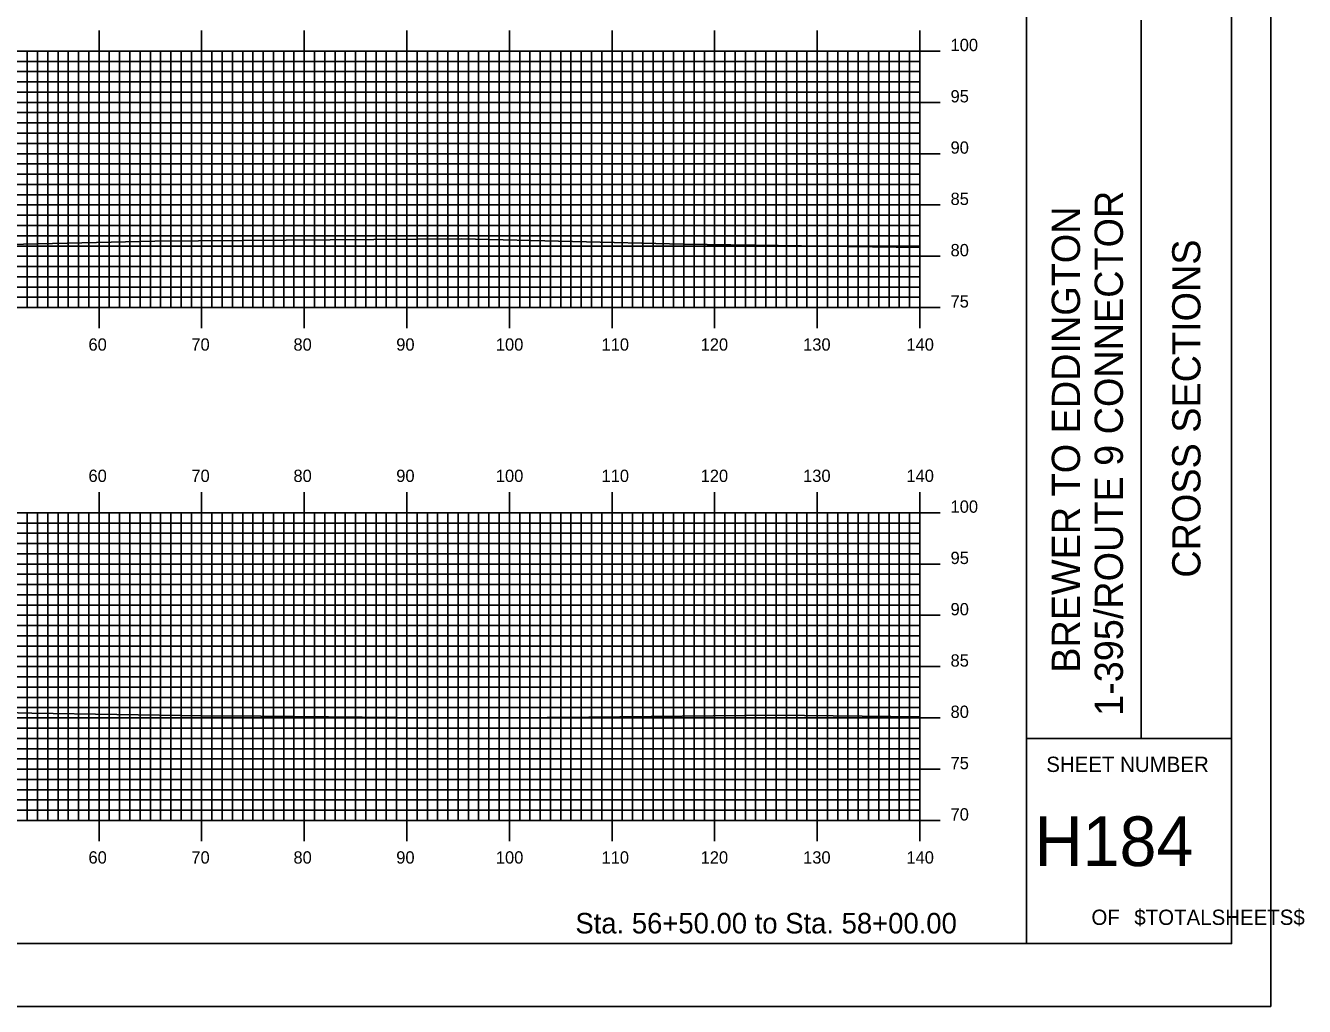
# Model space of a CAD drawing. Extents: x 1757069 to 1757412, y 442591 to 442811.
# Drawn here: x 1757287.4 to 1757412.1, y 442590.5 to 442686.2 of the extents above; entities that cross this region are included whole.
import ezdxf

# ---------------------------------------------------------------- set-up
doc = ezdxf.new("R2010")
doc.units = 0
for name, color, linetype in [('BORDER', 7, 'Continuous'), ('H_V ANNOTATION', 7, 'Continuous'), ('MAJOR', 7, 'Continuous'), ('MINOR', 7, 'Continuous'), ('PLOT BOUNDARY', 7, 'Continuous'), ('S_Roadway_Centerline', 7, 'Continuous')]:
    doc.layers.add(name, color=color, linetype=linetype)

msp = doc.modelspace()

# ---------------------------------------------------------------- linework, layer by layer
at = {"layer": 'BORDER'}
for p, q in [((1757385, 442596.67), (1757385, 442806.67)), ((1757396.18, 442616.67), (1757396.18, 442686.67)), ((1757385, 442616.67), (1757405, 442616.67))]:
    msp.add_line(p, q, dxfattribs=at)
msp.add_lwpolyline([(1757085, 442596.67), (1757405, 442596.67), (1757405, 442806.67), (1757085, 442806.67)], close=True, dxfattribs=at)
at = {"layer": 'MAJOR'}
for p, q in [((1757294.6, 442685.67), (1757294.6, 442683.67)), ((1757304.6, 442685.67), (1757304.6, 442683.67)), ((1757314.6, 442685.67), (1757314.6, 442683.67)), ((1757324.6, 442685.67), (1757324.6, 442683.67)), ((1757334.6, 442685.67), (1757334.6, 442683.67)), ((1757344.6, 442685.67), (1757344.6, 442683.67)), ((1757354.6, 442685.67), (1757354.6, 442683.67)), ((1757364.6, 442685.67), (1757364.6, 442683.67)), ((1757374.6, 442685.67), (1757374.6, 442683.67)), ((1757094.6, 442683.67), (1757374.6, 442683.67)), ((1757094.6, 442683.67), (1757374.6, 442683.67)), ((1757294.6, 442658.67), (1757294.6, 442683.67)), ((1757304.6, 442658.67), (1757304.6, 442683.67)), ((1757314.6, 442658.67), (1757314.6, 442683.67)), ((1757324.6, 442658.67), (1757324.6, 442683.67)), ((1757334.6, 442658.67), (1757334.6, 442683.67)), ((1757344.6, 442658.67), (1757344.6, 442683.67)), ((1757354.6, 442658.67), (1757354.6, 442683.67)), ((1757364.6, 442658.67), (1757364.6, 442683.67)), ((1757376.6, 442683.67), (1757372.59, 442683.67)), ((1757374.6, 442658.67), (1757374.6, 442683.67)), ((1757374.6, 442658.67), (1757374.6, 442683.67)), ((1757094.6, 442678.67), (1757374.6, 442678.67)), ((1757376.6, 442678.67), (1757372.59, 442678.67)), ((1757094.6, 442673.67), (1757374.6, 442673.67)), ((1757376.6, 442673.67), (1757372.59, 442673.67)), ((1757094.6, 442668.67), (1757374.6, 442668.67)), ((1757376.6, 442668.67), (1757372.59, 442668.67)), ((1757094.6, 442663.67), (1757374.6, 442663.67)), ((1757376.6, 442663.67), (1757372.59, 442663.67)), ((1757094.6, 442658.67), (1757374.6, 442658.67)), ((1757094.6, 442658.67), (1757374.6, 442658.67)), ((1757294.6, 442656.66), (1757294.6, 442658.67)), ((1757304.6, 442656.66), (1757304.6, 442658.67)), ((1757314.6, 442656.66), (1757314.6, 442658.67)), ((1757324.6, 442656.66), (1757324.6, 442658.67)), ((1757334.6, 442656.66), (1757334.6, 442658.67)), ((1757344.6, 442656.66), (1757344.6, 442658.67)), ((1757354.6, 442656.66), (1757354.6, 442658.67)), ((1757364.6, 442656.66), (1757364.6, 442658.67)), ((1757376.6, 442658.67), (1757372.59, 442658.67)), ((1757374.6, 442656.66), (1757374.6, 442658.67)), ((1757294.6, 442640.67), (1757294.6, 442638.67)), ((1757304.6, 442640.67), (1757304.6, 442638.67)), ((1757314.6, 442640.67), (1757314.6, 442638.67)), ((1757324.6, 442640.67), (1757324.6, 442638.67)), ((1757334.6, 442640.67), (1757334.6, 442638.67)), ((1757344.6, 442640.67), (1757344.6, 442638.67)), ((1757354.6, 442640.67), (1757354.6, 442638.67)), ((1757364.6, 442640.67), (1757364.6, 442638.67)), ((1757374.6, 442640.67), (1757374.6, 442638.67)), ((1757094.6, 442638.67), (1757374.6, 442638.67)), ((1757094.6, 442638.67), (1757374.6, 442638.67)), ((1757294.6, 442608.67), (1757294.6, 442638.67)), ((1757304.6, 442608.67), (1757304.6, 442638.67)), ((1757314.6, 442608.67), (1757314.6, 442638.67)), ((1757324.6, 442608.67), (1757324.6, 442638.67)), ((1757334.6, 442608.67), (1757334.6, 442638.67)), ((1757344.6, 442608.67), (1757344.6, 442638.67)), ((1757354.6, 442608.67), (1757354.6, 442638.67)), ((1757364.6, 442608.67), (1757364.6, 442638.67)), ((1757376.6, 442638.67), (1757372.59, 442638.67)), ((1757374.6, 442608.67), (1757374.6, 442638.67)), ((1757374.6, 442608.67), (1757374.6, 442638.67)), ((1757094.6, 442633.67), (1757374.6, 442633.67)), ((1757376.6, 442633.67), (1757372.59, 442633.67)), ((1757094.6, 442628.67), (1757374.6, 442628.67)), ((1757376.6, 442628.67), (1757372.59, 442628.67)), ((1757094.6, 442623.67), (1757374.6, 442623.67)), ((1757376.6, 442623.67), (1757372.59, 442623.67)), ((1757094.6, 442618.67), (1757374.6, 442618.67)), ((1757376.6, 442618.67), (1757372.59, 442618.67)), ((1757094.6, 442613.67), (1757374.6, 442613.67)), ((1757376.6, 442613.67), (1757372.59, 442613.67)), ((1757094.6, 442608.67), (1757374.6, 442608.67)), ((1757094.6, 442608.67), (1757374.6, 442608.67)), ((1757294.6, 442606.66), (1757294.6, 442608.67)), ((1757304.6, 442606.66), (1757304.6, 442608.67)), ((1757314.6, 442606.66), (1757314.6, 442608.67)), ((1757324.6, 442606.66), (1757324.6, 442608.67)), ((1757334.6, 442606.66), (1757334.6, 442608.67)), ((1757344.6, 442606.66), (1757344.6, 442608.67)), ((1757354.6, 442606.66), (1757354.6, 442608.67)), ((1757364.6, 442606.66), (1757364.6, 442608.67)), ((1757376.6, 442608.67), (1757372.59, 442608.67)), ((1757374.6, 442606.66), (1757374.6, 442608.67))]:
    msp.add_line(p, q, dxfattribs=at)
at = {"layer": 'MINOR'}
for p, q in [((1757287.6, 442658.67), (1757287.6, 442683.67)), ((1757288.6, 442658.67), (1757288.6, 442683.67)), ((1757289.6, 442658.67), (1757289.6, 442683.67)), ((1757290.6, 442658.67), (1757290.6, 442683.67)), ((1757291.6, 442658.67), (1757291.6, 442683.67)), ((1757292.6, 442658.67), (1757292.6, 442683.67)), ((1757293.6, 442658.67), (1757293.6, 442683.67)), ((1757295.6, 442658.67), (1757295.6, 442683.67)), ((1757296.6, 442658.67), (1757296.6, 442683.67)), ((1757297.6, 442658.67), (1757297.6, 442683.67)), ((1757298.6, 442658.67), (1757298.6, 442683.67)), ((1757299.6, 442658.67), (1757299.6, 442683.67)), ((1757300.6, 442658.67), (1757300.6, 442683.67)), ((1757301.6, 442658.67), (1757301.6, 442683.67)), ((1757302.6, 442658.67), (1757302.6, 442683.67)), ((1757303.6, 442658.67), (1757303.6, 442683.67)), ((1757305.6, 442658.67), (1757305.6, 442683.67)), ((1757306.6, 442658.67), (1757306.6, 442683.67)), ((1757307.6, 442658.67), (1757307.6, 442683.67)), ((1757308.6, 442658.67), (1757308.6, 442683.67)), ((1757309.6, 442658.67), (1757309.6, 442683.67)), ((1757310.6, 442658.67), (1757310.6, 442683.67)), ((1757311.6, 442658.67), (1757311.6, 442683.67)), ((1757312.6, 442658.67), (1757312.6, 442683.67)), ((1757313.6, 442658.67), (1757313.6, 442683.67)), ((1757315.6, 442658.67), (1757315.6, 442683.67)), ((1757316.6, 442658.67), (1757316.6, 442683.67)), ((1757317.6, 442658.67), (1757317.6, 442683.67)), ((1757318.6, 442658.67), (1757318.6, 442683.67)), ((1757319.6, 442658.67), (1757319.6, 442683.67)), ((1757320.6, 442658.67), (1757320.6, 442683.67)), ((1757321.6, 442658.67), (1757321.6, 442683.67)), ((1757322.6, 442658.67), (1757322.6, 442683.67)), ((1757323.6, 442658.67), (1757323.6, 442683.67)), ((1757325.6, 442658.67), (1757325.6, 442683.67)), ((1757326.6, 442658.67), (1757326.6, 442683.67)), ((1757327.6, 442658.67), (1757327.6, 442683.67)), ((1757328.6, 442658.67), (1757328.6, 442683.67)), ((1757329.6, 442658.67), (1757329.6, 442683.67)), ((1757330.6, 442658.67), (1757330.6, 442683.67)), ((1757331.6, 442658.67), (1757331.6, 442683.67)), ((1757332.6, 442658.67), (1757332.6, 442683.67)), ((1757333.6, 442658.67), (1757333.6, 442683.67)), ((1757335.6, 442658.67), (1757335.6, 442683.67)), ((1757336.6, 442658.67), (1757336.6, 442683.67)), ((1757337.6, 442658.67), (1757337.6, 442683.67)), ((1757338.6, 442658.67), (1757338.6, 442683.67)), ((1757339.6, 442658.67), (1757339.6, 442683.67)), ((1757340.6, 442658.67), (1757340.6, 442683.67)), ((1757341.6, 442658.67), (1757341.6, 442683.67)), ((1757342.6, 442658.67), (1757342.6, 442683.67)), ((1757343.6, 442658.67), (1757343.6, 442683.67)), ((1757345.6, 442658.67), (1757345.6, 442683.67)), ((1757346.6, 442658.67), (1757346.6, 442683.67)), ((1757347.6, 442658.67), (1757347.6, 442683.67)), ((1757348.6, 442658.67), (1757348.6, 442683.67)), ((1757349.6, 442658.67), (1757349.6, 442683.67)), ((1757350.6, 442658.67), (1757350.6, 442683.67)), ((1757351.6, 442658.67), (1757351.6, 442683.67)), ((1757352.6, 442658.67), (1757352.6, 442683.67)), ((1757353.6, 442658.67), (1757353.6, 442683.67)), ((1757355.6, 442658.67), (1757355.6, 442683.67)), ((1757356.6, 442658.67), (1757356.6, 442683.67)), ((1757357.6, 442658.67), (1757357.6, 442683.67)), ((1757358.6, 442658.67), (1757358.6, 442683.67)), ((1757359.6, 442658.67), (1757359.6, 442683.67)), ((1757360.6, 442658.67), (1757360.6, 442683.67)), ((1757361.6, 442658.67), (1757361.6, 442683.67)), ((1757362.6, 442658.67), (1757362.6, 442683.67)), ((1757363.6, 442658.67), (1757363.6, 442683.67)), ((1757365.6, 442658.67), (1757365.6, 442683.67)), ((1757366.6, 442658.67), (1757366.6, 442683.67)), ((1757367.6, 442658.67), (1757367.6, 442683.67)), ((1757368.6, 442658.67), (1757368.6, 442683.67)), ((1757369.6, 442658.67), (1757369.6, 442683.67)), ((1757370.6, 442658.67), (1757370.6, 442683.67)), ((1757371.6, 442658.67), (1757371.6, 442683.67)), ((1757372.6, 442658.67), (1757372.6, 442683.67)), ((1757373.6, 442658.67), (1757373.6, 442683.67)), ((1757094.6, 442682.67), (1757374.6, 442682.67)), ((1757374.6, 442682.67), (1757372.59, 442682.67)), ((1757094.6, 442681.67), (1757374.6, 442681.67)), ((1757374.6, 442681.67), (1757372.59, 442681.67)), ((1757094.6, 442680.67), (1757374.6, 442680.67)), ((1757374.6, 442680.67), (1757372.59, 442680.67)), ((1757094.6, 442679.67), (1757374.6, 442679.67)), ((1757374.6, 442679.67), (1757372.59, 442679.67)), ((1757094.6, 442677.67), (1757374.6, 442677.67)), ((1757374.6, 442677.67), (1757372.59, 442677.67)), ((1757094.6, 442676.67), (1757374.6, 442676.67)), ((1757374.6, 442676.67), (1757372.59, 442676.67)), ((1757094.6, 442675.67), (1757374.6, 442675.67)), ((1757374.6, 442675.67), (1757372.59, 442675.67)), ((1757094.6, 442674.67), (1757374.6, 442674.67)), ((1757374.6, 442674.67), (1757372.59, 442674.67)), ((1757094.6, 442672.67), (1757374.6, 442672.67)), ((1757374.6, 442672.67), (1757372.59, 442672.67)), ((1757094.6, 442671.67), (1757374.6, 442671.67)), ((1757374.6, 442671.67), (1757372.59, 442671.67)), ((1757094.6, 442670.67), (1757374.6, 442670.67)), ((1757374.6, 442670.67), (1757372.59, 442670.67)), ((1757094.6, 442669.67), (1757374.6, 442669.67)), ((1757374.6, 442669.67), (1757372.59, 442669.67)), ((1757094.6, 442667.67), (1757374.6, 442667.67)), ((1757374.6, 442667.67), (1757372.59, 442667.67)), ((1757094.6, 442666.67), (1757374.6, 442666.67)), ((1757374.6, 442666.67), (1757372.59, 442666.67)), ((1757094.6, 442665.67), (1757374.6, 442665.67)), ((1757374.6, 442665.67), (1757372.59, 442665.67)), ((1757094.6, 442664.67), (1757374.6, 442664.67)), ((1757374.6, 442664.67), (1757372.59, 442664.67)), ((1757094.6, 442662.67), (1757374.6, 442662.67)), ((1757374.6, 442662.67), (1757372.59, 442662.67)), ((1757094.6, 442661.67), (1757374.6, 442661.67)), ((1757374.6, 442661.67), (1757372.59, 442661.67)), ((1757094.6, 442660.67), (1757374.6, 442660.67)), ((1757374.6, 442660.67), (1757372.59, 442660.67)), ((1757094.6, 442659.67), (1757374.6, 442659.67)), ((1757374.6, 442659.67), (1757372.59, 442659.67)), ((1757094.6, 442637.67), (1757374.6, 442637.67)), ((1757287.6, 442608.67), (1757287.6, 442638.67)), ((1757288.6, 442608.67), (1757288.6, 442638.67)), ((1757289.6, 442608.67), (1757289.6, 442638.67)), ((1757290.6, 442608.67), (1757290.6, 442638.67)), ((1757291.6, 442608.67), (1757291.6, 442638.67)), ((1757292.6, 442608.67), (1757292.6, 442638.67)), ((1757293.6, 442608.67), (1757293.6, 442638.67)), ((1757295.6, 442608.67), (1757295.6, 442638.67)), ((1757296.6, 442608.67), (1757296.6, 442638.67)), ((1757297.6, 442608.67), (1757297.6, 442638.67)), ((1757298.6, 442608.67), (1757298.6, 442638.67)), ((1757299.6, 442608.67), (1757299.6, 442638.67)), ((1757300.6, 442608.67), (1757300.6, 442638.67)), ((1757301.6, 442608.67), (1757301.6, 442638.67)), ((1757302.6, 442608.67), (1757302.6, 442638.67)), ((1757303.6, 442608.67), (1757303.6, 442638.67)), ((1757305.6, 442608.67), (1757305.6, 442638.67)), ((1757306.6, 442608.67), (1757306.6, 442638.67)), ((1757307.6, 442608.67), (1757307.6, 442638.67)), ((1757308.6, 442608.67), (1757308.6, 442638.67)), ((1757309.6, 442608.67), (1757309.6, 442638.67)), ((1757310.6, 442608.67), (1757310.6, 442638.67)), ((1757311.6, 442608.67), (1757311.6, 442638.67)), ((1757312.6, 442608.67), (1757312.6, 442638.67)), ((1757313.6, 442608.67), (1757313.6, 442638.67)), ((1757315.6, 442608.67), (1757315.6, 442638.67)), ((1757316.6, 442608.67), (1757316.6, 442638.67)), ((1757317.6, 442608.67), (1757317.6, 442638.67)), ((1757318.6, 442608.67), (1757318.6, 442638.67)), ((1757319.6, 442608.67), (1757319.6, 442638.67)), ((1757320.6, 442608.67), (1757320.6, 442638.67)), ((1757321.6, 442608.67), (1757321.6, 442638.67)), ((1757322.6, 442608.67), (1757322.6, 442638.67)), ((1757323.6, 442608.67), (1757323.6, 442638.67)), ((1757325.6, 442608.67), (1757325.6, 442638.67)), ((1757326.6, 442608.67), (1757326.6, 442638.67)), ((1757327.6, 442608.67), (1757327.6, 442638.67)), ((1757328.6, 442608.67), (1757328.6, 442638.67)), ((1757329.6, 442608.67), (1757329.6, 442638.67)), ((1757330.6, 442608.67), (1757330.6, 442638.67)), ((1757331.6, 442608.67), (1757331.6, 442638.67)), ((1757332.6, 442608.67), (1757332.6, 442638.67)), ((1757333.6, 442608.67), (1757333.6, 442638.67)), ((1757335.6, 442608.67), (1757335.6, 442638.67)), ((1757336.6, 442608.67), (1757336.6, 442638.67)), ((1757337.6, 442608.67), (1757337.6, 442638.67)), ((1757338.6, 442608.67), (1757338.6, 442638.67)), ((1757339.6, 442608.67), (1757339.6, 442638.67)), ((1757340.6, 442608.67), (1757340.6, 442638.67)), ((1757341.6, 442608.67), (1757341.6, 442638.67)), ((1757342.6, 442608.67), (1757342.6, 442638.67)), ((1757343.6, 442608.67), (1757343.6, 442638.67)), ((1757345.6, 442608.67), (1757345.6, 442638.67)), ((1757346.6, 442608.67), (1757346.6, 442638.67)), ((1757347.6, 442608.67), (1757347.6, 442638.67)), ((1757348.6, 442608.67), (1757348.6, 442638.67)), ((1757349.6, 442608.67), (1757349.6, 442638.67)), ((1757350.6, 442608.67), (1757350.6, 442638.67)), ((1757351.6, 442608.67), (1757351.6, 442638.67)), ((1757352.6, 442608.67), (1757352.6, 442638.67)), ((1757353.6, 442608.67), (1757353.6, 442638.67)), ((1757355.6, 442608.67), (1757355.6, 442638.67)), ((1757356.6, 442608.67), (1757356.6, 442638.67)), ((1757357.6, 442608.67), (1757357.6, 442638.67)), ((1757358.6, 442608.67), (1757358.6, 442638.67)), ((1757359.6, 442608.67), (1757359.6, 442638.67)), ((1757360.6, 442608.67), (1757360.6, 442638.67)), ((1757361.6, 442608.67), (1757361.6, 442638.67)), ((1757362.6, 442608.67), (1757362.6, 442638.67)), ((1757363.6, 442608.67), (1757363.6, 442638.67)), ((1757365.6, 442608.67), (1757365.6, 442638.67)), ((1757366.6, 442608.67), (1757366.6, 442638.67)), ((1757367.6, 442608.67), (1757367.6, 442638.67)), ((1757368.6, 442608.67), (1757368.6, 442638.67)), ((1757369.6, 442608.67), (1757369.6, 442638.67)), ((1757370.6, 442608.67), (1757370.6, 442638.67)), ((1757371.6, 442608.67), (1757371.6, 442638.67)), ((1757374.6, 442637.67), (1757372.59, 442637.67)), ((1757372.6, 442608.67), (1757372.6, 442638.67)), ((1757373.6, 442608.67), (1757373.6, 442638.67)), ((1757094.6, 442636.67), (1757374.6, 442636.67)), ((1757374.6, 442636.67), (1757372.59, 442636.67)), ((1757094.6, 442635.67), (1757374.6, 442635.67)), ((1757374.6, 442635.67), (1757372.59, 442635.67)), ((1757094.6, 442634.67), (1757374.6, 442634.67)), ((1757374.6, 442634.67), (1757372.59, 442634.67)), ((1757094.6, 442632.67), (1757374.6, 442632.67)), ((1757374.6, 442632.67), (1757372.59, 442632.67)), ((1757094.6, 442631.67), (1757374.6, 442631.67)), ((1757374.6, 442631.67), (1757372.59, 442631.67)), ((1757094.6, 442630.67), (1757374.6, 442630.67)), ((1757374.6, 442630.67), (1757372.59, 442630.67)), ((1757094.6, 442629.67), (1757374.6, 442629.67)), ((1757374.6, 442629.67), (1757372.59, 442629.67)), ((1757094.6, 442627.67), (1757374.6, 442627.67)), ((1757374.6, 442627.67), (1757372.59, 442627.67)), ((1757094.6, 442626.67), (1757374.6, 442626.67)), ((1757374.6, 442626.67), (1757372.59, 442626.67)), ((1757094.6, 442625.67), (1757374.6, 442625.67)), ((1757374.6, 442625.67), (1757372.59, 442625.67)), ((1757094.6, 442624.67), (1757374.6, 442624.67)), ((1757374.6, 442624.67), (1757372.59, 442624.67)), ((1757094.6, 442622.67), (1757374.6, 442622.67)), ((1757374.6, 442622.67), (1757372.59, 442622.67)), ((1757094.6, 442621.67), (1757374.6, 442621.67)), ((1757374.6, 442621.67), (1757372.59, 442621.67)), ((1757094.6, 442620.67), (1757374.6, 442620.67)), ((1757374.6, 442620.67), (1757372.59, 442620.67)), ((1757094.6, 442619.67), (1757374.6, 442619.67)), ((1757374.6, 442619.67), (1757372.59, 442619.67)), ((1757094.6, 442617.67), (1757374.6, 442617.67)), ((1757374.6, 442617.67), (1757372.59, 442617.67)), ((1757094.6, 442616.67), (1757374.6, 442616.67)), ((1757374.6, 442616.67), (1757372.59, 442616.67)), ((1757094.6, 442615.67), (1757374.6, 442615.67)), ((1757374.6, 442615.67), (1757372.59, 442615.67)), ((1757094.6, 442614.67), (1757374.6, 442614.67)), ((1757374.6, 442614.67), (1757372.59, 442614.67)), ((1757094.6, 442612.67), (1757374.6, 442612.67)), ((1757374.6, 442612.67), (1757372.59, 442612.67)), ((1757094.6, 442611.67), (1757374.6, 442611.67)), ((1757374.6, 442611.67), (1757372.59, 442611.67)), ((1757094.6, 442610.67), (1757374.6, 442610.67)), ((1757374.6, 442610.67), (1757372.59, 442610.67)), ((1757094.6, 442609.67), (1757374.6, 442609.67)), ((1757374.6, 442609.67), (1757372.59, 442609.67))]:
    msp.add_line(p, q, dxfattribs=at)
at = {"layer": 'PLOT BOUNDARY'}
msp.add_lwpolyline([(1757068.81, 442590.55), (1757408.81, 442590.55), (1757408.81, 442810.55), (1757068.81, 442810.55)], close=True, dxfattribs=at)
at = {"layer": 'S_Roadway_Centerline'}
for points in [[(1757094.6, 442664.18), (1757094.81, 442664.19), (1757104.62, 442664.24), (1757118.38, 442664.3), (1757139.82, 442664.37), (1757152.51, 442664.44), (1757175.36, 442664.55), (1757195.7, 442664.74), (1757219.61, 442665.15), (1757229.73, 442665.24), (1757247.02, 442664.86), (1757252.08, 442664.77), (1757253.32, 442664.76), (1757254.57, 442664.75), (1757285.8, 442664.81), (1757300.04, 442665.14), (1757329.94, 442665.38), (1757351.56, 442664.86), (1757374.6, 442664.54)], [(1757094.6, 442619.18), (1757096.35, 442619.19), (1757115.03, 442619.28), (1757138.2, 442619.39), (1757141.93, 442619.4), (1757145.49, 442619.42), (1757176.97, 442619.81), (1757201.32, 442619.7), (1757201.96, 442619.71), (1757202.39, 442619.71), (1757227.35, 442619.94), (1757258.33, 442619.75), (1757260.69, 442619.72), (1757265.63, 442619.7), (1757288.04, 442619.12), (1757304.62, 442618.87), (1757310.38, 442618.84), (1757330.15, 442618.65), (1757342.34, 442618.73), (1757360.53, 442618.93), (1757374.6, 442618.78)]]:
    msp.add_lwpolyline(points, dxfattribs=at)

# ---------------------------------------------------------------- texts
at = {"layer": 'BORDER'}
for s, p in [('1-395/ROUTE 9 CONNECTOR', (1757394.4, 442618.87)), ('BREWER TO EDDINGTON', (1757390.22, 442623.07)), ('CROSS SECTIONS', (1757401.96, 442632.34))]:
    msp.add_text(s, height=2.7557, rotation=90, dxfattribs=at).set_placement(p)
for s, height, p in [('SHEET NUMBER', 1.4905, (1757386.93, 442613.4)), ('H184', 4.839, (1757385.8, 442604.23)), ('$TOTALSHEETS$', 1.4905, (1757395.51, 442598.49)), ('OF', 1.491, (1757391.33, 442598.49))]:
    msp.add_text(s, height=height, dxfattribs=at).set_placement(p)
at = {"layer": 'H_V ANNOTATION'}
for s, height, p in [('100', 1.2, (1757377.6, 442683.67)), ('95', 1.2, (1757377.6, 442678.67)), ('90', 1.2, (1757377.6, 442673.67)), ('85', 1.2, (1757377.6, 442668.67)), ('80', 1.2, (1757377.6, 442663.67)), ('75', 1.2, (1757377.6, 442658.67)), ('60', 1.2, (1757293.57, 442654.47)), ('70', 1.2, (1757303.6, 442654.47)), ('80', 1.2, (1757313.55, 442654.47)), ('90', 1.2, (1757323.57, 442654.47)), ('100', 1.2, (1757333.28, 442654.47)), ('110', 1.2, (1757343.58, 442654.47)), ('120', 1.2, (1757353.24, 442654.47)), ('130', 1.2, (1757363.23, 442654.47)), ('140', 1.2, (1757373.3, 442654.47)), ('60', 1.2, (1757293.57, 442641.67)), ('70', 1.2, (1757303.6, 442641.67)), ('80', 1.2, (1757313.55, 442641.67)), ('90', 1.2, (1757323.57, 442641.67)), ('100', 1.2, (1757333.28, 442641.67)), ('110', 1.2, (1757343.58, 442641.67)), ('120', 1.2, (1757353.24, 442641.67)), ('130', 1.2, (1757363.23, 442641.67)), ('140', 1.2, (1757373.3, 442641.67)), ('100', 1.2, (1757377.6, 442638.67)), ('95', 1.2, (1757377.6, 442633.67)), ('90', 1.2, (1757377.6, 442628.67)), ('85', 1.2, (1757377.6, 442623.67)), ('80', 1.2, (1757377.6, 442618.67)), ('75', 1.2, (1757377.6, 442613.67)), ('70', 1.2, (1757377.6, 442608.67)), ('60', 1.2, (1757293.57, 442604.47)), ('70', 1.2, (1757303.6, 442604.47)), ('80', 1.2, (1757313.55, 442604.47)), ('90', 1.2, (1757323.57, 442604.47)), ('100', 1.2, (1757333.28, 442604.47)), ('110', 1.2, (1757343.58, 442604.47)), ('120', 1.2, (1757353.24, 442604.47)), ('130', 1.2, (1757363.23, 442604.47)), ('140', 1.2, (1757373.3, 442604.47)), ('Sta. 56+50.00 to Sta. 58+00.00', 2.0004, (1757341.03, 442597.66))]:
    msp.add_text(s, height=height, dxfattribs=at).set_placement(p)

doc.saveas('drawing.dxf')
